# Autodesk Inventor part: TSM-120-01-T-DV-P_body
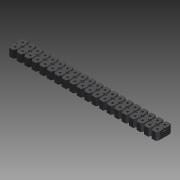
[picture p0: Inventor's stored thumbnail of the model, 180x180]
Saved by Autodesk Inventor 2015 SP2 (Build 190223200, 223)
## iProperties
Category: PARTsolutions
Company: SAMTEC
Created: 2015-08
Part Number: TSM-120-01-T-DV-P_body
Catalog Web Link: www.cadenas.de
Description: TSM Series Body-TSM Series - (2,54 mm) .100" Surface Mount Terminal .025" Square Post Header
Vendor: SAMTEC
Document SubType Name: Modeling
Designer: PARTuser1
Manufacturer: SAMTEC
Mass: 0.492067 g
Surface Area: 13.1563 cm^2
Volume: 0.492067 cm^3
Density: 1 g/cm^3
Material: Allgemein
Appearance: PSOLRGB-127-127-127
PSOL_IDENT_0: {$CADENAS_DATA\23d-libs\samtec\modelling\tsm\parts\tsm_body.prj},251 {VTYP=3D},{NB=TSM-120-01-T-DV-P
PSOL_IDENT_1: _body},{LINA=TSM-120-01-T-DV-P_body},{NN=TSM Series Body},{DATE=20.05.2015 13:50:20},{GEOMDATE=20.05
PSOL_IDENT_2: .2015 06:27:00},{VERSION=},{LINEID=10},{LINESUBID=-1},{WBVAR=POS,LS,ROW,PLOPT,LCOPT,AOPT,SLOPT,POLOP
PSOL_IDENT_3: T,POPT,TROPT,KOPT}  {NB=TSM-120-01-T-DV-P_body},{LINA=TSM-120-01-T-DV-P_body},{KT=DUMMY},{PN=TSM-120
PSOL_IDENT_4: -01-T-DV-P},{SERIES=TSM},{POS=20},{POSPN=20},{LS=-01},{LSALG= '-01','-01','-02','-02','-03','-03','-
PSOL_IDENT_5: 04','-04' ,'-05','-05 (Non-standard option -  Please contact SAMTEC)' },{ROW=-DV},{ROWALG= '-SV','-S
PSOL_IDENT_6: V - Single Vertical', '-SH','-SH - Single Horizontal', '-DV' ,'-DV - Double Vertical' ,'-DV-S' ,'-DV
PSOL_IDENT_7: -S - Double Vertical Molded End Shrouds (Non-standard option -  Please contact SAMTEC)', '-DH', '-DH
PSOL_IDENT_8: - Double Horizontal' ,  '-MT','-MT - Mixed Technology','-EM','-EM - Edge Mount', '-TM','-TM - Tripl
PSOL_IDENT_9: e Mixed Technology'  },{PLOPT=-T},{PLOPTALG= '-T','-T - Matte Tin on Entire Pin','-S','-S - 30micro\
PSOL_IDENT_10: " Selective Gold in Contact Area, Matte Tin on Tail','-G','-G - 10micro\" Selective Gold in Contact
PSOL_IDENT_11: Area, 3micro\" Selective Gold on Tail','-L','-L - 10micro\" Selective Gold in Contact Area, Matte Ti
PSOL_IDENT_12: n on Tail','-TL','-TL - Tin/Lead (90/10) on Entire Pin','-STL','-STL - 30micro\" Selective Gold in C
PSOL_IDENT_13: ontact Area, Tin/Lead (90/10) on Tail','-F','-F - 3micro\" Selective Gold in Contact Area, Matte Tin
PSOL_IDENT_14: on Tail','-H','-H - 30micro\" Selective Gold in Contact Area, Matte Tin on Tail','-TM','-TM - Matte
PSOL_IDENT_15: Tin on Entire Pin','-SM','-SM - 30micro\" Selective Gold in Contact Area, Matte Tin on Tail','-LM','
PSOL_IDENT_16: -LM - 10micro\" Selective Gold in Contact Area, Matte Tin on Tail','-FM','-FM - 3micro\" Selective G
PSOL_IDENT_17: old in Contact Area, Matte Tin on Tail','-SS','-SS - 30micro\" Stripe Selective Gold in Contact Area
PSOL_IDENT_18: , Matte Tin on Tail' },{LCOPT=},{LCOPTALG= '','Not Selected','-LC','-LC - Locking Clip' },{AOPT=},{A
PSOL_IDENT_19: OPTALG= '','Not Selected','-A' , '-A - Alignment Pin'  },{SLOPT=},{SLOPTALG= '','Not Available' },{P
PSOL_IDENT_20: OLOPT=},{POLOPTALG= '','Not Selected','001','001','002','002','003','003','004','004','005','005','0
PSOL_IDENT_21: 06','006','007','007','008','008','009','009','010','010','011','011','012','012','013','013','014','
PSOL_IDENT_22: 014','015','015','016','016','017','017','018','018','019','019','020','020','021','021','022','022'
PSOL_IDENT_23: ,'023','023','024','024','025','025','026','026','027','027','028','028','029','029','030','030','03
PSOL_IDENT_24: 1','031','032','032','033','033','034','034','035','035','036','036','037','037','038','038','039','
PSOL_IDENT_25: 039','040','040' },{POLOPTMAX=480},{POLOPTMAX2='001','001','002','002','003','003','004','004','005'
PSOL_IDENT_26: ,'005','006','006','007','007','008','008','009','009','010','010','011','011','012','012','013','01
PSOL_IDENT_27: 3','014','014','015','015','016','016','017','017','018','018','019','019','020','020','021','021','
PSOL_IDENT_28: 022','022','023','023','024','024','025','025','026','026','027','027','028','028','029','029','030'
PSOL_IDENT_29: ,'030','031','031','032','032','033','033','034','034','035','035','036','036','037','037','038','03
PSOL_IDENT_30: 8','039','039','040','040'},{POLARIZE='001','001','002','002','003','003','004','004','005','005','0
PSOL_IDENT_31: 06','006','007','007','008','008','009','009','010','010','011','011','012','012','013','013','014','
PSOL_IDENT_32: 014','015','015','016','016','017','017','018','018','019','019','020','020','021','021','022','022'
PSOL_IDENT_33: ,'023','023','024','024','025','025','026','026','027','027','028','028','029','029','030','030','03
PSOL_IDENT_34: 1','031','032','032','033','033','034','034','035','035','036','036','037','037','038','038','039','
PSOL_IDENT_35: 039','040','040','041','041','042','042','043','043','044','044','045','045','046','046','047','047'
PSOL_IDENT_36: ,'048','048','049','049','050','050','051','051','052','052','053','053','054','054','055','055','05
PSOL_IDENT_37: 6','056','057','057','058','058','059','059','060','060','061','061','062','062','063','063','064','
PSOL_IDENT_38: 064','065','065','066','066','067','067','068','068','069','069','070','070','071','071','072','072'
PSOL_IDENT_39: ,'073','073','074','074','075','075','076','076','077','077','078','078','079','079','080','080','08
PSOL_IDENT_40: 1','081','082','082','083','083','084','084','085','085','086','086','087','087','088','088','089','
PSOL_IDENT_41: 089','090','090','091','091','092','092','093','093','094','094','095','095','096','096','097','097'
PSOL_IDENT_42: ,'098','098','099','099','100','100','101','101','102','102','103','103','104','104','105','105','10
PSOL_IDENT_43: 6','106','107','107','108','108','109','109','110','110','111','111','112','112','113','113','114','
PSOL_IDENT_44: 114','115','115','116','116','117','117','118','118','119','119','120','120','121','121','122','122'
PSOL_IDENT_45: ,'123','123','124','124','125','125','126','126','127','127','128','128','129','129','130','130','13
PSOL_IDENT_46: 1','131','132','132','133','133','134','134','135','135','136','136','137','137','138','138','139','
PSOL_IDENT_47: 139','140','140','141','141','142','142','143','143','144','144','145','145','146','146','147','147'
PSOL_IDENT_48: ,'148','148','149','149','150','150'},{POLOPTPN=},{POPT=-P},{POPTALG= '','Not Selected','-P','-P - P
PSOL_IDENT_49: ick & Place Pad' },{TROPT=},{TROPTALG= '','Not Selected','-TR','-TR - Tape & Reel' },{KOPT=},{KOPTAL
PSOL_IDENT_50: G= '','Not Available' },{BSH=0.230},{CSH=0.180},{ESH=0.1000},{ASH=0.9000},{RSH=2.00000},{SSH=0.90155
PSOL_IDENT_51: },{ASV=0.80000},{BSV=0.230},{CSV=0.280},{DMAXSV=0.208},{ESV=0.445},{FSV=0.165},{CDHMT=0.230},{BDVTM=
PSOL_IDENT_52: 0.23000},{CDV=0.30300},{DDV=0.28000},{GDV=0.80500}
NN: TSM Series Body
NT: TSM Series - (2,54 mm) .100" Surface Mount Terminal .025" Square Post Header
NB: TSM-120-01-T-DV-P_body
NBSYN: $PN._body
LINA: TSM-120-01-T-DV-P_body
SERIES: TSM
POS: 20
LS: -01
ROW: -DV - Double Vertical
PLOPT: -T - Matte Tin on Entire Pin
LCOPT: Not Selected
AOPT: Not Selected
SLOPT: Not Available
POLOPT: Not Selected
POPT: -P - Pick & Place Pad
TROPT: Not Selected
KOPT: Not Available
SUPPLIER: SAMTEC
ARTICLENO: TSM-120-01-T-DV-P_body
BOMINFO: TSM-120-01-T-DV-P_body
CREATOR: CADENAS GmbH
Title: TSM-120-01-T-DV-P_body
Author: Cadenas PARTsolutions
Comments: TSM Series - (2,54 mm) .100" Surface Mount Terminal .025" Square Post Header
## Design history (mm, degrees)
sketch "Sketch_1"
  geometry: L1 (-0.699, 0.762)-(-0.699, -0.762); L2 (-0.699, -0.762)-(0.699, -0.762); L3 (0.699, -0.762)-(0.699, 0.762); L4 (0.699, 0.762)-(-0.699, 0.762)
  constraints: 8 end point
extrude "Extrusion1" join sketch "Sketch_1" stored distance "d0" = 50.8; taper "d1" = 0 deg
sketch "Sketch_2"
  geometry: L1 (25.209, 0.146)-(25.209, 1.651); L2 (25.209, 1.651)-(24.829, 2.54); L3 (24.829, 2.54)-(23.431, 2.54); L4 (23.431, 2.54)-(23.05, 1.651); L5 (23.05, 1.651)-(23.05, 0.146); L6 (23.05, 0.146)-(23.495, 0.146); L7 (23.495, 0.146)-(23.495, -0.146); L8 (23.495, -0.146)-(23.05, -0.146); L9 (23.05, -0.146)-(23.05, -1.651); L10 (23.05, -1.651)-(23.431, -2.54); L11 (23.431, -2.54)-(24.829, -2.54); L12 (24.829, -2.54)-(25.209, -1.651); L13 (25.209, -1.651)-(25.209, -0.146); L14 (25.209, -0.146)-(24.765, -0.146); L15 (24.765, -0.146)-(24.765, 0.146); L16 (24.765, 0.146)-(25.209, 0.146); L17 (24.448, 1.587)-(23.812, 1.587); L18 (23.812, 1.587)-(23.812, 0.953); L19 (23.812, 0.953)-(24.448, 0.953); L20 (24.448, 0.953)-(24.448, 1.587); L21 (24.448, -0.953)-(23.812, -0.953); L22 (23.812, -0.953)-(23.812, -1.587); L23 (23.812, -1.587)-(24.448, -1.587); L24 (24.448, -1.587)-(24.448, -0.953)
  constraints: 48 end point
extrude "Extrusion2" join sketch "Sketch_2" stored distance "d2" = 2.54; taper "d3" = 0 deg
node "body_XY"
node "body_YZ"
node "body_ZX"
node "body_X"
node "body_Y"
node "body_Z"
node "body_Center"
node "pick_place_pad_XY"
node "pick_place_pad_YZ"
node "pick_place_pad_ZX"
node "pick_place_pad_X"
node "pick_place_pad_Y"
node "pick_place_pad_Z"
node "pick_place_pad_Center"
node "terminal_dv_XY"
node "terminal_dv_YZ"
node "terminal_dv_ZX"
node "terminal_dv_X"
node "terminal_dv_Y"
node "terminal_dv_Z"
node "terminal_dv_Center"
body "Solid1"
pattern_linear "Rectangular Pattern1" dims "d6" = 2.54, "d9" = 0
